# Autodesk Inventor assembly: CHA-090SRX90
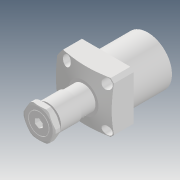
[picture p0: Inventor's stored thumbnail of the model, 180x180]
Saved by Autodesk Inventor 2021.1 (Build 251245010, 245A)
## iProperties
Created: 2019-05
Part Number: CHA-090SRX90
Description: STEP AP203
Document SubType Name: Assembly
Designer: user
Title: CHA-090SRX90.STEP
Revision Number: ÈÎºÎ
Sending System: SolidWorks 2017
Preprocessor: SwSTEP 2.0
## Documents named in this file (5)
- D:\Vault_2016\Projekty\Clamptek\Hydraulic\CHA\CHA\CHA-090\Inventor\CHA-090SRX90\CHA-090SRX90.iam
- D:\Vault_2016\Projekty\Clamptek\Hydraulic\CHA\CHA\CHA-090\Inventor\CHA-090SRX90\CHA-090±¾Ìå.ipt
- D:\Vault_2016\Projekty\Clamptek\Hydraulic\CHA\CHA\CHA-090\Inventor\CHA-090SRX90\CHA-090S»îÈû¸Ë.ipt
- D:\Vault_2016\Projekty\Clamptek\Hydraulic\CHA\CHA\CHA-090\Inventor\CHA-090SRX90\CHA-090S×¶Ì×.ipt
- D:\Vault_2016\Projekty\Clamptek\Hydraulic\CHA\CHA\CHA-090\Inventor\CHA-090SRX90\CHA-090ÂÝÄ¸.ipt
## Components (4 placed, 4 different names)
1. CHA-090±¾Ìå_1
2. CHA-090S»îÈû¸Ë_2
3. CHA-090S×¶Ì×_3
4. CHA-090ÂÝÄ¸_4
